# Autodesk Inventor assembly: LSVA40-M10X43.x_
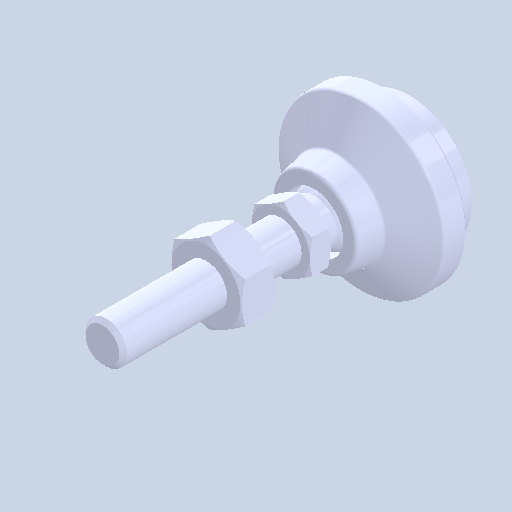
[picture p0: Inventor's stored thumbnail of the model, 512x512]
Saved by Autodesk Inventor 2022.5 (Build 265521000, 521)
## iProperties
Created: 2024-08
Part Number: LSVA40-M10X43.x_
Document SubType Name: Assembly
Designer: ImaoCorp
Author: ImaoCorp
Sending System: SOLIDWORKS 2022-2022290
MC: AMD64
MC_MODEL: Intel64 Family 6 Model 60 Stepping 3, GenuineIntel
OS: Windows_NT
FRU: Parasolid Version 33.1, build 260,  4-25-2022
FORMAT: text
GUISE: transmit
KEY: FILELSVA40-M10X43.x_t
DATE: Fri Aug 23 16:07:12 2024
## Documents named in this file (4)
- X:\14_SW2022-Inv2022\06_2024-10新製品(SME)\ELS_データ\l\lsva40-m10x43\LSVA40-M10X43.x_.iam
- X:\14_SW2022-Inv2022\06_2024-10新製品(SME)\ELS_データ\l\lsva40-m10x43\LSVA40-M10X43_01.ipt
- X:\14_SW2022-Inv2022\06_2024-10新製品(SME)\ELS_データ\l\lsva40-m10x43\LSVA40-M10X43_02.ipt
- X:\14_SW2022-Inv2022\06_2024-10新製品(SME)\ELS_データ\l\lsva40-m10x43\LSVA40-M10X43_03.ipt
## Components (3 placed, 3 different names)
1. LSVA40-M10X43_01
2. LSVA40-M10X43_02
3. LSVA40-M10X43_03
